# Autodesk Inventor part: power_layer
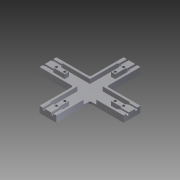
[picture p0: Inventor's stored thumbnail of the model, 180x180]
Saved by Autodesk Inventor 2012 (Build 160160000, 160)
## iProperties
Created: 2011-06
Part Number: power_layer
Document SubType Name: Modeling
Designer: Bruce
Density: 1 g/cm^3
Material: Default
Author: Bruce
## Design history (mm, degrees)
sketch "Sketch1"
  geometry: L1 (-50, 50)-(50, 50); L2 (50, 50)-(50, -50); L3 (50, -50)-(-50, -50); L4 (-50, -50)-(-50, 50); L5 (-50, 0)-(50, 0); L6 (0, 50)-(0, -50); L7 (-10, 50)-(-10, 10); L8 (-10, 10)-(-50, 10); L9 (10, 50)-(10, 10); L10 (10, 10)-(50, 10); L11 (50, -10)-(10, -10); L12 (10, -10)-(10, -50); L13 (-10, -50)-(-10, -10); L14 (-10, -10)-(-50, -10); L15 (-10, 50)-(10, 50); L16 (50, 10)-(50, -10); L17 (10, -50)-(-10, -50); L18 (-50, 10)-(-50, -10); 1 further point
  constraints: 36 end point, 8 point on line, 6 perpendicular, 5 parallel, 4 collinear, 4 midpoint, 1 horizontal
  dimensions: "d0" = 50 distance from line of L1 point (0, 0) (= 0.5 x hub_square); "d1" = 50 distance from line of L3 point (0, 0) (= 0.5 x hub_square); "d2" = 50 distance from line of L2 point (0, 0) (= 0.5 x hub_square); "d3" = 50 distance from line of point (0, 0) L4 (= 0.5 x hub_square); "d4" = 10 distance between parallel lines of L6 L7 (= 0.5 x arm_width + structural_cover); "d5" = 10 distance between parallel lines of L6 L9 (= 0.5 x arm_width + structural_cover); "d6" = 10 distance between parallel lines of L5 L8 (= 0.5 x arm_width + structural_cover); "d7" = 10 distance between parallel lines of L14 L5 (= 0.5 x arm_width + structural_cover); "d8" = 10 distance between parallel lines of L6 L13 (= 0.5 x arm_width + structural_cover); "d9" = 10 distance between parallel lines of L12 L6 (= 0.5 x arm_width + structural_cover); "d10" = 10 distance between parallel lines of L11 L5 (= 0.5 x arm_width + structural_cover); "d11" = 10 distance between parallel lines of L10 L5 (= 0.5 x arm_width + structural_cover)
extrude "Extrusion1" new body sketch "Sketch1" distance "d12" = 2.5 (= structural_cover); taper "d13" = 0 deg
sketch "Sketch2"
  geometry: L1 (-10, 50)-(10, 50) reference; L2 (-10, 10)-(-10, 50) reference; L3 (-50, 10)-(-10, 10) reference; L4 (-50, -10)-(-50, 10) reference; L5 (-10, -10)-(-50, -10) reference; L6 (-10, -50)-(-10, -10) reference; L7 (10, -50)-(-10, -50) reference; L8 (10, -10)-(10, -50) reference; L9 (50, -10)-(10, -10) reference; L10 (50, 10)-(50, -10) reference; L11 (10, 10)-(50, 10) reference; L12 (10, 50)-(10, 10) reference; L13 (-7.5, 50)-(-7.5, 7.5); L14 (-7.5, 7.5)-(-50, 7.5); L15 (-50, -7.5)-(-7.5, -7.5); L16 (-7.5, -7.5)-(-7.5, -50); L17 (50, -7.5)-(7.5, -7.5); L18 (7.5, -7.5)-(7.5, -50); L19 (50, 7.5)-(7.5, 7.5); L20 (7.5, 7.5)-(7.5, 50); L21 (-7.5, 50)-(-10, 50); L22 (-10, 10)-(-50, 10); L23 (-50, 7.5)-(-50, 10); L24 (-50, -7.5)-(-50, -10); L25 (-50, -10)-(-10, -10); L26 (-10, -10)-(-10, -50); L27 (-10, -50)-(-7.5, -50); L28 (7.5, -50)-(10, -50); L29 (10, -50)-(10, -10); L30 (10, -10)-(50, -10); L31 (50, -10)-(50, -7.5); L32 (50, 7.5)-(50, 10); L33 (50, 10)-(10, 10); L34 (10, 10)-(10, 50); L35 (10, 50)-(7.5, 50); L36 (-10, 50)-(-10, 10); L37 (-50, 0)-(50, 0); L38 (0, 50)-(0, -50); L39 (-27.5, 7.5)-(-27.5, -7.5); L40 (-7.5, 27.5)-(7.5, 27.5); L41 (27.5, 7.5)-(27.5, -7.5); L42 (-7.5, -27.5)-(7.5, -27.5); 1 further point
  constraints: 60 end point, 16 point on line, 13 collinear, 13 perpendicular, 4 midpoint, 2 parallel
  dimensions: "d14" = 2.5 distance between parallel lines of L13 L2 (= structural_cover); "d15" = 2.5 distance between parallel lines of L14 L3 (= structural_cover); "d16" = 2.5 distance between parallel lines of L5 L15 (= structural_cover); "d17" = 2.5 distance between parallel lines of L16 L6 (= structural_cover); "d18" = 2.5 distance between parallel lines of L8 L18 (= structural_cover); "d19" = 2.5 distance between parallel lines of L9 L17 (= structural_cover); "d20" = 2.5 distance between parallel lines of L19 L11 (= structural_cover); "d21" = 2.5 distance between parallel lines of L12 L20 (= structural_cover); "d82" = 22.5 distance between parallel lines of L39 L4 (= 2 x arm_fixing_spacing + structural_cover); "d83" = 22.5 distance between parallel lines of L1 L40 (= 2 x arm_fixing_spacing + structural_cover); "d84" = 22.5 distance between parallel lines of L10 L41 (= 2 x arm_fixing_spacing + structural_cover); "d85" = 22.5 distance between parallel lines of L7 L42 (= 2 x arm_fixing_spacing + structural_cover)
extrude "Extrusion2" join sketch "Sketch2" distance "d22" = 5 (= power_thickness); taper "d23" = 0 deg
sketch "Sketch3"
  geometry: L1 (-10, 50)-(10, 50) reference; L2 (-50, -10)-(-50, 10) reference; L3 (10, -50)-(-10, -50) reference; L4 (50, 10)-(50, -10) reference; L5 (0, 50)-(0, -50); L6 (-50, 0)-(50, 0); C1 r 1.5 at (-40, 0); C2 r 1.5 at (-30, 0); C3 r 1.5 at (0, 40); C4 r 1.5 at (0, 30); C5 r 1.5 at (0, -40); C6 r 1.5 at (0, -30); C7 r 1.5 at (40, 0); C8 r 1.5 at (30, 0); 1 further point
  constraints: 8 centre point, 8 point on line, 4 end point, 4 midpoint
  dimensions: "d24" = 3 diameter of C1 (= arm_bolt_diam); "d25" = 3 diameter of C2 (= arm_bolt_diam); "d26" = 3 diameter of C3 (= arm_bolt_diam); "d27" = 3 diameter of C4 (= arm_bolt_diam); "d28" = 3 diameter of C8 (= arm_bolt_diam); "d29" = 3 diameter of C7 (= arm_bolt_diam); "d30" = 3 diameter of C6 (= arm_bolt_diam); "d31" = 3 diameter of C5 (= arm_bolt_diam); "d32" = 10 distance from line of C1.centre L2 (= arm_fixing_spacing); "d33" = 10 distance of C2.centre C1.centre (= arm_fixing_spacing); "d34" = 10 distance from line of L1 C3.centre (= arm_fixing_spacing); "d35" = 10 distance of C3.centre C4.centre (= arm_fixing_spacing); "d36" = 10 distance from line of L4 C7.centre (= arm_fixing_spacing); "d37" = 10 distance of C7.centre C8.centre (= arm_fixing_spacing); "d38" = 10 distance of C5.centre C6.centre (= arm_fixing_spacing); "d39" = 10 distance from line of C5.centre L3 (= arm_fixing_spacing)
extrude "Extrusion3" cut sketch "Sketch3" distance "d40" = 7.5 (= structural_cover + power_thickness); taper "d41" = 0 deg
sketch "Sketch6"
  geometry: L1 (-7.5, -27.5)-(7.5, -27.5) reference; L2 (-27.5, 7.5)-(-27.5, -7.5) reference; L3 (7.5, 27.5)-(-7.5, 27.5) reference; L4 (27.5, -7.5)-(27.5, 7.5) reference; L5 (50, 10)-(50, -10) reference; L6 (-10, 50)-(10, 50) reference; L7 (-50, -10)-(-50, 10) reference; L8 (10, -50)-(-10, -50) reference; L9 (-50, -5)-(-27.5, -5); L10 (-50, 5)-(-27.5, 5); L11 (-5, -50)-(-5, -27.5); L12 (5, -50)-(5, -27.5); L13 (-5, 27.5)-(-5, 50); L14 (5, 27.5)-(5, 50); L15 (27.5, -5)-(50, -5); L16 (27.5, 5)-(50, 5); L17 (-27.5, 6.25)-(-50, 6.25); L18 (-50, -3.75)-(-27.5, -3.75); L19 (-50, -6.25)-(-27.5, -6.25); L20 (-50, 3.75)-(-27.5, 3.75); L21 (-6.25, -27.5)-(-6.25, -50); L22 (-3.75, -27.5)-(-3.75, -50); L23 (3.75, -27.5)-(3.75, -50); L24 (6.25, -27.5)-(6.25, -50); L25 (27.5, 6.25)-(50, 6.25); L26 (27.5, 3.75)-(50, 3.75); L27 (27.5, -3.75)-(50, -3.75); L28 (27.5, -6.25)-(50, -6.25); L29 (-6.25, 50)-(-6.25, 27.5); L30 (-3.75, 50)-(-3.75, 27.5); L31 (3.75, 50)-(3.75, 27.5); L32 (6.25, 50)-(6.25, 27.5); C1 r 1.5 at (-30, 0) reference; C2 r 1.5 at (0, -30) reference; C3 r 1.5 at (0, 40) reference; C4 r 1.5 at (40, 0) reference; 1 further point
  constraints: 48 end point, 48 point on line, 23 perpendicular, 1 parallel
  dimensions: "d86" = 5 distance from line of L13 C3.centre (derived); "d87" = 5 distance from line of L14 C3.centre (derived); "d88" = 5 distance from line of L16 C4.centre (derived); "d89" = 5 distance from line of L15 C4.centre (derived); "d90" = 5 distance from line of L9 C1.centre (derived); "d91" = 5 distance from line of L10 C1.centre (derived); "d92" = 5 distance from line of L11 C2.centre (derived); "d93" = 5 distance from line of L12 C2.centre (derived); "d94" = 1.25 distance between parallel lines of L13 L29 (= 0.5 x bullet_diam); "d95" = 1.25 distance between parallel lines of L30 L13 (= 0.5 x bullet_diam); "d96" = 1.25 distance between parallel lines of L14 L31 (= 0.5 x bullet_diam); "d97" = 1.25 distance between parallel lines of L32 L14 (= 0.5 x bullet_diam); "d98" = 1.25 distance between parallel lines of L17 L10 (= 0.5 x bullet_diam); "d99" = 1.25 distance between parallel lines of L20 L10 (= 0.5 x bullet_diam); "d100" = 1.25 distance between parallel lines of L9 L18 (= 0.5 x bullet_diam); "d101" = 1.25 distance between parallel lines of L19 L9 (= 0.5 x bullet_diam); "d102" = 1.25 distance between parallel lines of L11 L21 (= 0.5 x bullet_diam); "d103" = 1.25 distance between parallel lines of L22 L11 (= 0.5 x bullet_diam); "d104" = 1.25 distance between parallel lines of L12 L23 (= 0.5 x bullet_diam); "d105" = 1.25 distance between parallel lines of L24 L12 (= 0.5 x bullet_diam); "d106" = 1.25 distance between parallel lines of L15 L27 (= 0.5 x bullet_diam); "d107" = 1.25 distance between parallel lines of L28 L15 (= 0.5 x bullet_diam); "d108" = 1.25 distance between parallel lines of L16 L25 (= 0.5 x bullet_diam); "d109" = 1.25 distance between parallel lines of L26 L16 (= 0.5 x bullet_diam)
extrude "Extrusion5" cut sketch "Sketch6" distance "d110" = 1.25 (= 0.5 x bullet_diam); taper "d111" = 0 deg
sketch "Sketch7"
  geometry: L1 (3.75, 3.75)-(1.25, 3.75) reference; L2 (13.75, 3.75)-(11.25, 3.75) reference; C1 r 1.25 at (2.5, 3.75); C2 r 1.25 at (12.5, 3.75); 1 further point
  constraints: 2 centre point, 2 midpoint
  dimensions: "d112" = 2.5 diameter of C1 (= bullet_diam); "d113" = 2.5 diameter of C2 (= bullet_diam)
sketch "Sketch8"
  geometry: L1 (3.75, 1.25)-(3.75, 3.75) reference; L2 (3.75, 11.25)-(3.75, 13.75) reference; C1 r 1.25 at (3.75, 12.5); C2 r 1.25 at (3.75, 2.5); 1 further point
  constraints: 2 centre point, 2 midpoint
  dimensions: "d114" = 2.5 diameter of C1 (= bullet_diam); "d115" = 2.5 diameter of C2 (= bullet_diam)
sketch "Sketch9"
  geometry: L1 (-3.75, 3.75)-(-3.75, 1.25) reference; L2 (-3.75, 13.75)-(-3.75, 11.25) reference; C1 r 1.25 at (-3.75, 12.5); C2 r 1.25 at (-3.75, 2.5); 1 further point
  constraints: 2 centre point, 2 midpoint
  dimensions: "d116" = 2.5 diameter of C1 (= bullet_diam); "d117" = 2.5 diameter of C2 (= bullet_diam)
sketch "Sketch10"
  geometry: L1 (1.25, -3.75)-(3.75, -3.75) reference; L2 (11.25, -3.75)-(13.75, -3.75) reference; C1 r 1.25 at (2.5, -3.75); C2 r 1.25 at (12.5, -3.75); 1 further point
  constraints: 2 centre point, 2 midpoint
  dimensions: "d118" = 2.5 diameter of C1 (= bullet_diam); "d119" = 2.5 diameter of C2 (= bullet_diam)
extrude "Extrusion6" cut sketch "Sketch10" distance "d120" = 22.5 (= 2 x arm_fixing_spacing + structural_cover); taper "d121" = 0 deg
extrude "Extrusion7" cut sketch "Sketch9" distance "d122" = 22.5 (= 2 x arm_fixing_spacing + structural_cover); taper "d123" = 0 deg
extrude "Extrusion8" cut sketch "Sketch8" distance "d124" = 22.5 (= 2 x arm_fixing_spacing + structural_cover); taper "d125" = 0 deg
extrude "Extrusion9" cut sketch "Sketch7" distance "d126" = 22.5 (= 2 x arm_fixing_spacing + structural_cover); taper "d127" = 0 deg
sketch "Sketch11"
  geometry: L1 (7.5, -7.5)-(27.5, -7.5) reference; L2 (7.5, -27.5)-(7.5, -7.5) reference; L3 (10, -10)-(10, -50) reference; L4 (50, -10)-(10, -10) reference; L5 (50, -6.25)-(50, -10) reference; L6 (7.5, -17.5)-(10, -17.5); L7 (17.5, -10)-(17.5, -7.5); 1 further point
  constraints: 4 end point, 2 midpoint, 2 perpendicular, 2 point on line
  dimensions: "d128" = 10 distance between parallel lines of L1 L6; "d129" = 10 distance between parallel lines of L2 L7
extrude "Extrusion10" cut sketch "Sketch11" distance "d130" = 5 (= power_thickness); taper "d131" = 0 deg
sketch "Sketch12"
  geometry: L1 (-27.5, 7.5)-(-27.5, -7.5) reference; L2 (-27.5, -7.5)-(-7.5, -7.5) reference; L3 (-7.5, -27.5)-(7.5, -27.5) reference; L4 (7.5, -27.5)-(7.5, -17.5) reference; L5 (27.5, -7.5)-(27.5, 7.5) reference; L6 (7.5, 7.5)-(7.5, 27.5) reference; L7 (7.5, 27.5)-(-7.5, 27.5) reference; L8 (-7.5, 7.5)-(-27.5, 7.5) reference; L9 (-7.5, 27.5)-(-7.5, 40); L10 (-7.5, 40)-(7.5, 40); L11 (7.5, 40)-(7.5, 27.5); L12 (-3.75, 50)-(3.75, 50) reference; L13 (-2.5, 40)-(-2.5, 27.5); L14 (2.5, 40)-(2.5, 27.5); L15 (-27.5, 7.5)-(-40, 7.5); L16 (-40, 7.5)-(-40, -7.5); L17 (-40, -7.5)-(-27.5, -7.5); L18 (-7.5, -27.5)-(-7.5, -40); L19 (-7.5, -40)-(7.5, -40); L20 (27.5, 7.5)-(40, 7.5); L21 (40, 7.5)-(40, -7.5); L22 (40, -7.5)-(27.5, -7.5); L23 (50, 3.75)-(50, -3.75) reference; L24 (-50, -3.75)-(-50, 3.75) reference; L25 (3.75, -50)-(-3.75, -50) reference; L26 (-40, 2.5)-(-27.5, 2.5); L27 (-40, -2.5)-(-27.5, -2.5); L28 (-2.5, -27.5)-(-2.5, -40); L29 (2.5, -27.5)-(2.5, -40); L30 (27.5, 2.5)-(40, 2.5); L31 (27.5, -2.5)-(40, -2.5); L32 (7.5, -40)-(7.5, -27.5); L33 (-27.5, 2.5)-(-27.5, 7.5); L34 (-27.5, -2.5)-(-27.5, -7.5); L35 (-7.5, -27.5)-(-2.5, -27.5); L36 (2.5, -27.5)-(7.5, -27.5); L37 (27.5, -2.5)-(27.5, -7.5); L38 (27.5, 7.5)-(27.5, 2.5); L39 (-2.5, 27.5)-(-7.5, 27.5); L40 (2.5, 27.5)-(7.5, 27.5); 1 further point
  constraints: 56 end point, 16 perpendicular, 16 point on line, 8 collinear, 3 parallel
  dimensions: "d132" = 10 distance between parallel lines of L10 L12 (computed from bullet_length); "d133" = 10 distance between parallel lines of L23 L21 (computed from bullet_length); "d134" = 10 distance between parallel lines of L24 L16 (computed from bullet_length); "d135" = 10 distance between parallel lines of L25 L19 (computed from bullet_length); "d136" = 5 distance between parallel lines of L9 L13 (= 0.5 x arm_width - structural_cover); "d137" = 5 distance between parallel lines of L11 L14 (= 0.5 x arm_width - structural_cover); "d138" = 5 distance between parallel lines of L20 L30 (= 0.5 x arm_width - structural_cover); "d139" = 5 distance between parallel lines of L22 L31 (= 0.5 x arm_width - structural_cover); "d140" = 5 distance between parallel lines of L32 L29 (= 0.5 x arm_width - structural_cover); "d141" = 5 distance between parallel lines of L18 L28 (= 0.5 x arm_width - structural_cover); "d142" = 5 distance between parallel lines of L15 L26 (= 0.5 x arm_width - structural_cover); "d143" = 5 distance between parallel lines of L17 L27 (= 0.5 x arm_width - structural_cover)
extrude "Extrusion11" cut sketch "Sketch12" distance "d144" = 5 (= power_thickness); taper "d145" = 0 deg
fillet "Fillet3" dims "d148" = 2
body "Solid1"
other parameters: "mounting_square" = 45 [user parameter], "arm_width" = 15 [user parameter; used in 16 equation terms], "arm_bolt_diam" = 3 [user parameter; used in 8 equation terms], "structural_cover" = 2.5 [user parameter; used in 34 equation terms], "pinch_gap" = 1 [user parameter], "arm_fixing_spacing" = 10 [user parameter; used in 16 equation terms], "mounting_bolt_diam" = 2 [user parameter], "bullet_diam" = 2.5 [user parameter; used in 25 equation terms], "bullet_length" = 15 [user parameter; used in 4 equation terms], "power_thickness" = 5 [user parameter; used in 4 equation terms]
